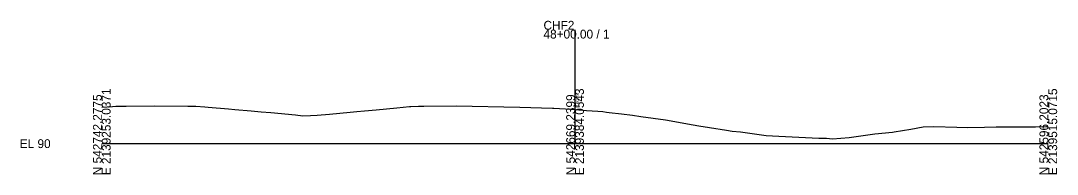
# Model space of a CAD drawing. Extents: x -12831 to 2303, y -10 to 39065.
# Drawn here: x 974.3 to 1302.8, y 35990.3 to 36038.9 of the extents above; entities that cross this region are included whole.
import ezdxf

# ---------------------------------------------------------------- set-up
doc = ezdxf.new("R2010")
doc.units = 0
for name, color, linetype in [('RD_GPK_XS_Cell', 7, 'Continuous'), ('RD_XS_ExGround', 7, 'Continuous'), ('RD_XS_TX_Elev_EX', 7, 'Continuous')]:
    doc.layers.add(name, color=color, linetype=linetype)

msp = doc.modelspace()

# ---------------------------------------------------------------- linework, layer by layer
at = {"layer": 'RD_GPK_XS_Cell'}
for p, q in [((1150, 36000), (1150, 36036.1)), ((1000, 36000), (1150, 36000)), ((1150, 36000), (1300, 36000))]:
    msp.add_line(p, q, dxfattribs=at)
at = {"layer": 'RD_XS_ExGround'}
for p, q in [((1000, 36011.58), (1003.42, 36011.78)), ((1003.42, 36011.78), (1004.49, 36011.84)), ((1004.49, 36011.84), (1007.72, 36011.89)), ((1007.72, 36011.89), (1016.86, 36012.03)), ((1016.86, 36012.03), (1027.22, 36011.91)), ((1027.22, 36011.91), (1029.79, 36011.88)), ((1029.79, 36011.88), (1032.7, 36011.64)), ((1032.7, 36011.64), (1033.72, 36011.56)), ((1033.72, 36011.56), (1040.11, 36010.98)), ((1040.11, 36010.98), (1042.13, 36010.78)), ((1042.13, 36010.78), (1047.31, 36010.38)), ((1083.27, 36010.4), (1086.95, 36010.74)), ((1086.95, 36010.74), (1093.48, 36011.35)), ((1093.48, 36011.35), (1097.51, 36011.73)), ((1097.51, 36011.73), (1097.91, 36011.77)), ((1097.91, 36011.77), (1100.38, 36011.87)), ((1100.38, 36011.87), (1100.76, 36011.87)), ((1100.76, 36011.87), (1102.02, 36011.89)), ((1102.02, 36011.89), (1112.35, 36012.03)), ((1112.35, 36012.03), (1132.49, 36011.52)), ((1132.49, 36011.52), (1142.82, 36011.27)), ((1142.82, 36011.27), (1143.32, 36011.23)), ((1143.32, 36011.23), (1148.81, 36010.88)), ((1148.81, 36010.88), (1150, 36010.78)), ((1150, 36010.78), (1153.59, 36010.52)), ((1153.59, 36010.52), (1157.27, 36010.28)), ((1047.31, 36010.38), (1050.52, 36010.08)), ((1050.52, 36010.08), (1053.59, 36009.83)), ((1053.59, 36009.83), (1061.44, 36009.08)), ((1061.44, 36009.08), (1063.69, 36008.83)), ((1063.69, 36008.83), (1066.14, 36008.91)), ((1066.14, 36008.91), (1068.28, 36009.01)), ((1068.28, 36009.01), (1072.2, 36009.36)), ((1072.2, 36009.36), (1078.72, 36010)), ((1078.72, 36010), (1080.82, 36010.2)), ((1080.82, 36010.2), (1083.27, 36010.4)), ((1157.27, 36010.28), (1158.76, 36010.15)), ((1158.76, 36010.15), (1159.95, 36010)), ((1159.95, 36010), (1160.8, 36009.89)), ((1160.8, 36009.89), (1164.71, 36009.44)), ((1164.71, 36009.44), (1168.24, 36009.03)), ((1168.24, 36009.03), (1170.86, 36008.63)), ((1170.86, 36008.63), (1178.7, 36007.54)), ((1178.7, 36007.54), (1187.4, 36005.99)), ((1187.4, 36005.99), (1189.26, 36005.64)), ((1189.26, 36005.64), (1192.61, 36005.11)), ((1192.61, 36005.11), (1197.97, 36004.27)), ((1197.97, 36004.27), (1199.8, 36004)), ((1199.8, 36004), (1202.44, 36003.75)), ((1251.15, 36003.76), (1256.45, 36004.59)), ((1256.45, 36004.59), (1260.33, 36005.31)), ((1260.33, 36005.31), (1263.74, 36005.39)), ((1263.74, 36005.39), (1271.05, 36005.25)), ((1271.05, 36005.25), (1274.3, 36005.16)), ((1274.3, 36005.16), (1279.79, 36005.23)), ((1279.79, 36005.23), (1283.45, 36005.32)), ((1283.45, 36005.32), (1284.8, 36005.36)), ((1284.8, 36005.36), (1287.85, 36005.33)), ((1287.85, 36005.33), (1295.9, 36005.38)), ((1295.9, 36005.38), (1299.38, 36005.42)), ((1299.38, 36005.42), (1300, 36005.42)), ((1202.44, 36003.75), (1206.17, 36003.17)), ((1206.17, 36003.17), (1210.55, 36002.57)), ((1210.55, 36002.57), (1214.63, 36002.41)), ((1214.63, 36002.41), (1227.28, 36001.77)), ((1227.28, 36001.77), (1227.95, 36001.76)), ((1227.95, 36001.76), (1229.73, 36001.72)), ((1229.73, 36001.72), (1231.62, 36001.49)), ((1231.62, 36001.49), (1236.9, 36001.9)), ((1236.9, 36001.9), (1242.85, 36002.79)), ((1242.85, 36002.79), (1244.98, 36003.08)), ((1244.98, 36003.08), (1250.6, 36003.62)), ((1250.6, 36003.62), (1251.15, 36003.76))]:
    msp.add_line(p, q, dxfattribs=at)

# ---------------------------------------------------------------- texts
at = {"layer": 'RD_GPK_XS_Cell'}
for s, p in [('CHF2', (1140, 36036.1)), ('48+00.00 / 1', (1140, 36033.3)), ('EL 90', (974, 35998.6))]:
    msp.add_text(s, height=2.8, dxfattribs=at).set_placement(p)
for s, p in [('E 2139253.0371', (1002.8, 35990)), ('E 2139384.0543', (1152.8, 35990)), ('E 2139515.0715', (1302.8, 35990)), ('N 542742.2775', (1000, 35990)), ('N 542669.2399', (1150, 35990)), ('N 542596.2023', (1300, 35990))]:
    msp.add_text(s, height=2.8, rotation=90, dxfattribs=at).set_placement(p)
at = {"layer": 'RD_XS_TX_Elev_EX'}
msp.add_text('100.78', height=1, rotation=90, dxfattribs=at).set_placement((1151.25, 36011.78))

doc.saveas('drawing.dxf')
